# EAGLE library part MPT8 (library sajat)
PHOENIX CONNECTOR
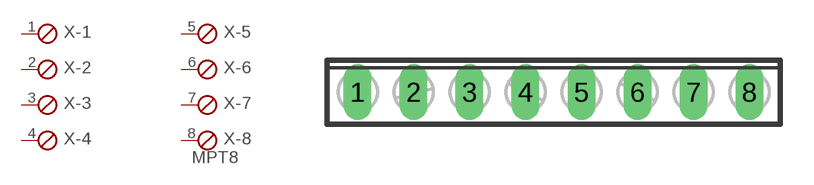
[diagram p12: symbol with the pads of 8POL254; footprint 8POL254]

Designator prefix X; gates -1=SKB -2=SKB -3=SKB -4=SKB -5=SKB -6=SKB -7=SKB -8=SKBV

## MPT8  [8POL254]
1  -1:1  pas
2  -2:1  pas
3  -3:1  pas
4  -4:1  pas
5  -5:1  pas
6  -6:1  pas
7  -7:1  pas
8  -8:1  pas

## Footprint 8POL254 (pad centres in mm)
PHOENIX CONNECTOR
drill 0.254 pad 1.27 long: 1 -8.89,0; 2 -6.35,0; 3 -3.81,0; 4 -1.27,0; 5 1.27,0; 6 3.81,0; 7 6.35,0; 8 8.89,0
